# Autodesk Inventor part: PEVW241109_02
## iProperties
Created: 2009-11
Part Number: PEVW241109_02
Cost Center: 0 kg
Material: 1.0037 St 37-2
Document SubType Name: Blech
Designer: Student_TAB
Authority: 0 mm^3
Density: 7.85 g/cm^3
Mass: 2093.51 g
Surface Area: 7196.38 cm^2
Volume: 266.689 cm^3
Description: Langlochteil
SaveDate: 2007-07-03
SaveTime: 10:26
TotalMass: 0 kg
TotalVolume: 0 mm^3
Author: Student_TAB
Title: Langlochteil
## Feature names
1. Spiegeln1 [Mirror]
2. Rechteckige Anordnung1 [Rectangular Pattern]
3. Grobblech1
4. Grobblech2
5. Biegung1
6. Ausklinkung1
